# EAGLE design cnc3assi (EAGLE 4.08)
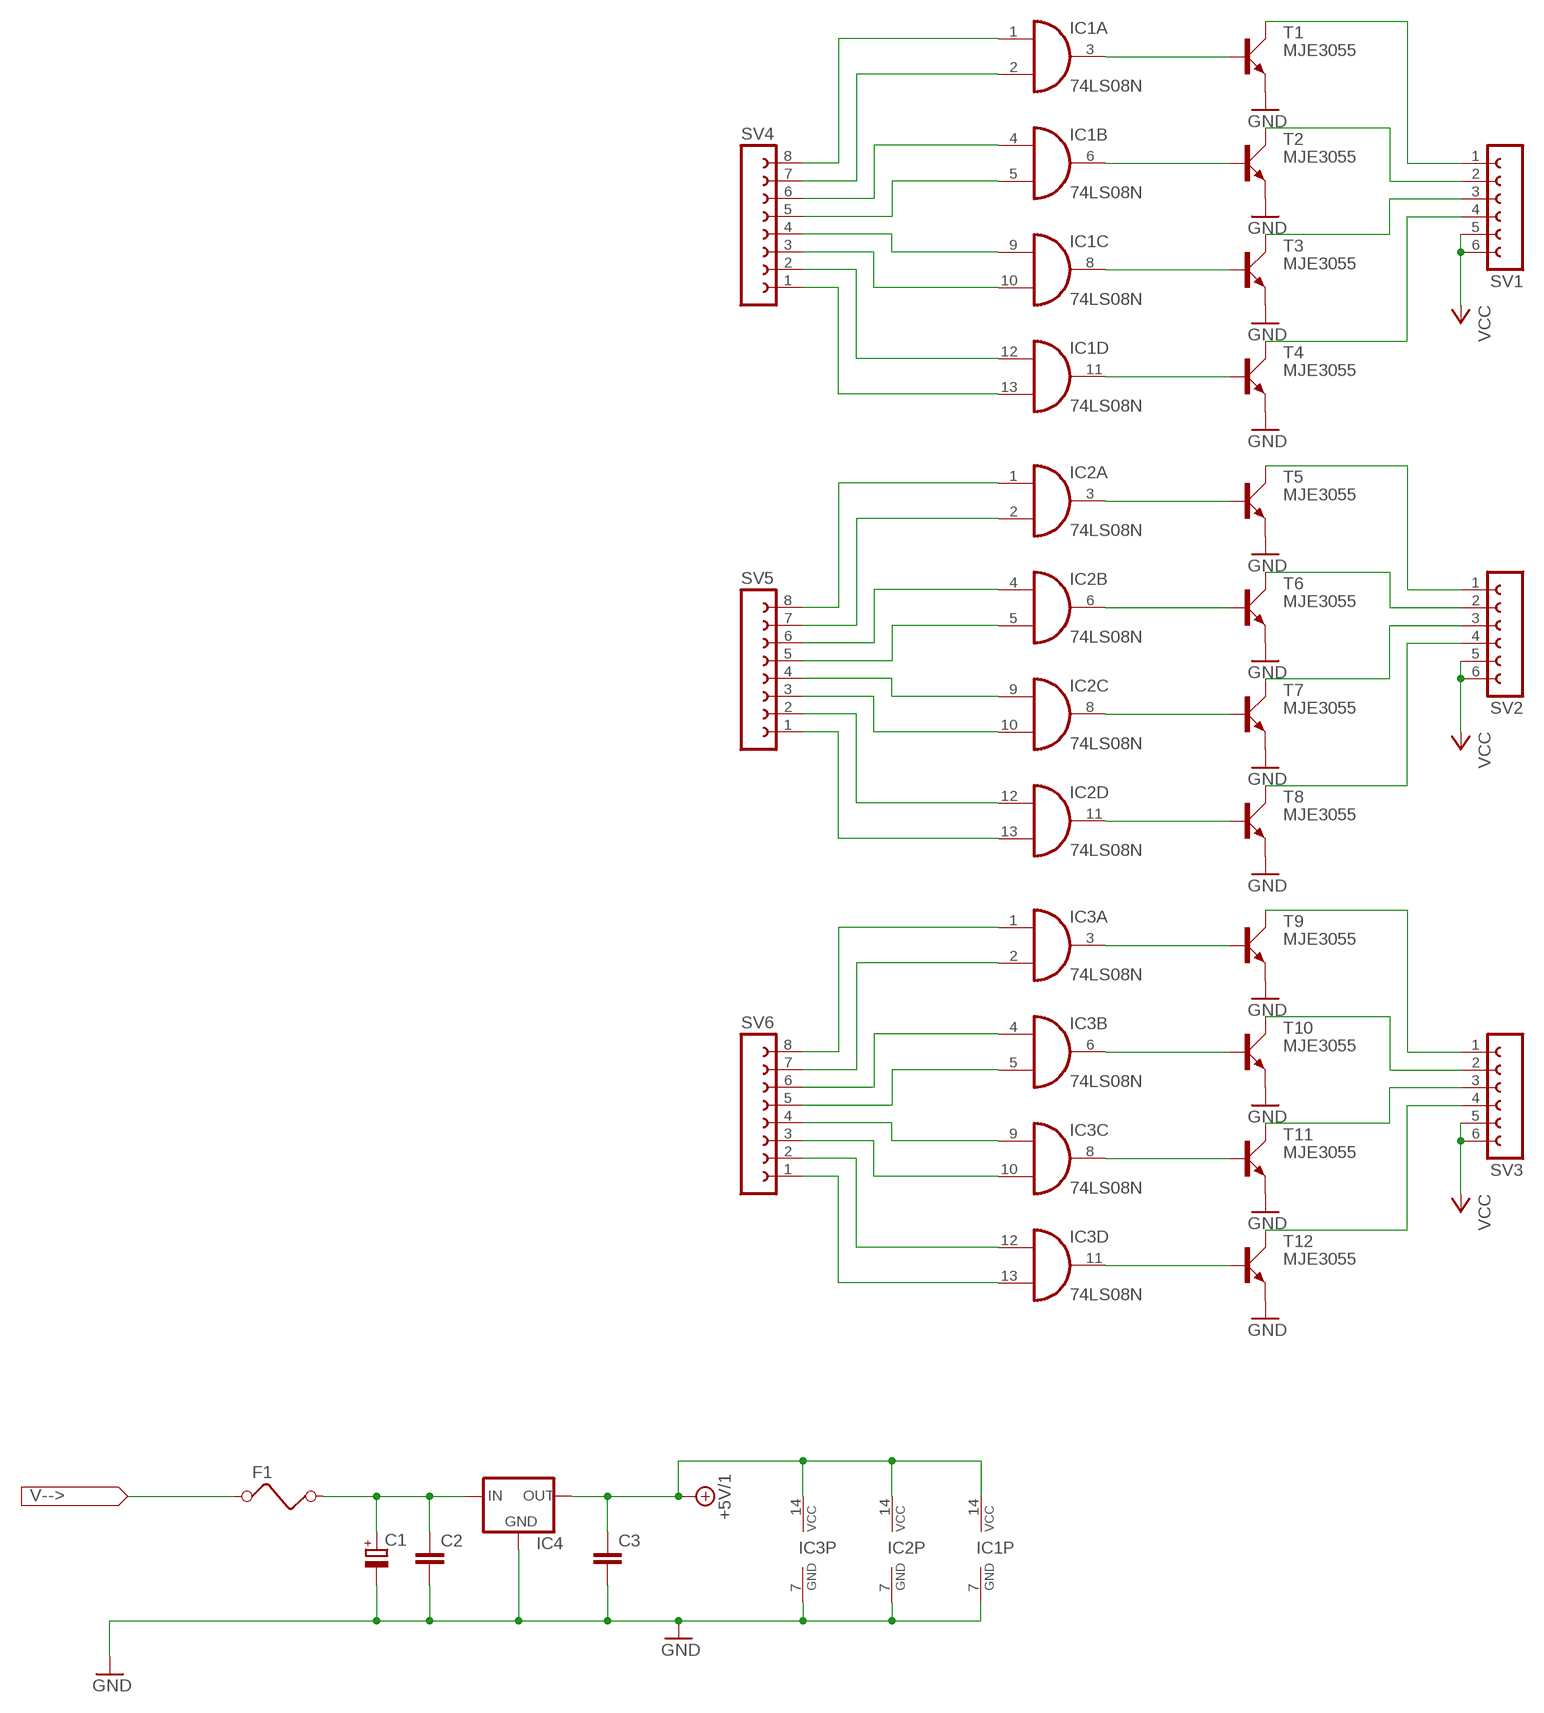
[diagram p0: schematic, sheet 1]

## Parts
C1  CPOL-EUE15-6AXIAL  [E15-6]
C2  C-EU025-030X050  [C025-030X050]
C3  C-EU025-030X050  [C025-030X050]
F1  FUSE  [FUSE]
IC1  74LS08N  [DIL14]
IC2  74LS08N  [DIL14]
IC3  74LS08N  [DIL14]
IC4  78XXS  [78XXS]
SV1  FE06-1  [FE06]
SV2  FE06-1  [FE06]
SV3  FE06-1  [FE06]
SV4  FE08-1  [FE08]
SV5  FE08-1  [FE08]
SV6  FE08-1  [FE08]
T1  MJE3055  [TO220AV]
T2  MJE3055  [TO220AV]
T3  MJE3055  [TO220AV]
T4  MJE3055  [TO220AV]
T5  MJE3055  [TO220AV]
T6  MJE3055  [TO220AV]
T7  MJE3055  [TO220AV]
T8  MJE3055  [TO220AV]
T9  MJE3055  [TO220AV]
T10  MJE3055  [TO220AV]
T11  MJE3055  [TO220AV]
T12  MJE3055  [TO220AV]

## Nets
+5V/1: C3.1 IC1.14(P:VCC) IC2.14(P:VCC) IC3.14(P:VCC) IC4.OUT
GND: C1.- C2.2 C3.2 IC1.7(P:GND) IC2.7(P:GND) IC3.7(P:GND) IC4.GND T1.E T2.E T3.E T4.E T5.E T6.E T7.E T8.E T9.E T10.E T11.E T12.E
N$1: IC1.3(A:O) T1.B
N$2: IC1.6(B:O) T2.B
N$3: IC1.8(C:O) T3.B
N$4: IC1.11(D:O) T4.B
N$5: IC2.3(A:O) T5.B
N$6: IC2.6(B:O) T6.B
N$7: IC2.8(C:O) T7.B
N$8: IC2.11(D:O) T8.B
N$9: IC3.3(A:O) T9.B
N$10: IC3.6(B:O) T10.B
N$11: IC3.8(C:O) T11.B
N$12: IC3.11(D:O) T12.B
N$13: SV1.1 T1.C
N$14: SV1.2 T2.C
N$15: SV1.3 T3.C
N$16: SV1.4 T4.C
N$17: SV2.1 T5.C
N$18: SV2.2 T6.C
N$19: SV2.3 T7.C
N$20: SV2.4 T8.C
N$21: SV3.1 T9.C
N$22: SV3.2 T10.C
N$23: SV3.3 T11.C
N$24: SV3.4 T12.C
N$25: IC1.1(A:I0) SV4.8
N$26: IC1.2(A:I1) SV4.7
N$27: IC1.4(B:I0) SV4.6
N$28: IC1.5(B:I1) SV4.5
N$29: IC1.13(D:I1) SV4.1
N$30: IC1.12(D:I0) SV4.2
N$31: IC1.10(C:I1) SV4.3
N$32: IC1.9(C:I0) SV4.4
N$33: IC2.1(A:I0) SV5.8
N$34: IC2.2(A:I1) SV5.7
N$35: IC2.4(B:I0) SV5.6
N$36: IC2.5(B:I1) SV5.5
N$37: IC2.13(D:I1) SV5.1
N$38: IC2.12(D:I0) SV5.2
N$39: IC2.10(C:I1) SV5.3
N$40: IC2.9(C:I0) SV5.4
N$41: IC3.1(A:I0) SV6.8
N$42: IC3.2(A:I1) SV6.7
N$43: IC3.4(B:I0) SV6.6
N$44: IC3.5(B:I1) SV6.5
N$45: IC3.13(D:I1) SV6.1
N$46: IC3.12(D:I0) SV6.2
N$47: IC3.10(C:I1) SV6.3
N$48: IC3.9(C:I0) SV6.4
N$49: F1.1
N$50: C1.+ C2.1 F1.2 IC4.IN
VCC: SV1.5 SV1.6 SV2.5 SV2.6 SV3.5 SV3.6

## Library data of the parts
C1 = rcl:CPOL-EU: POLARIZED CAPACITOR, European symbol
C2 C3 = rcl:C-EU: CAPACITOR, European symbol
F1 = special:FUSE: FUSE
IC1-IC3 = 74xx-eu:74*08: Quad 2-input AND gate
IC4 = v-reg:78XXS: VOLTAGE REGULATOR
SV1-SV3 = con-lsta:FE06-1: FEMALE HEADER
SV4-SV6 = con-lsta:FE08-1: FEMALE HEADER
T1-T12 = transistor-power:MJE3055: NPN TRANSISTOR

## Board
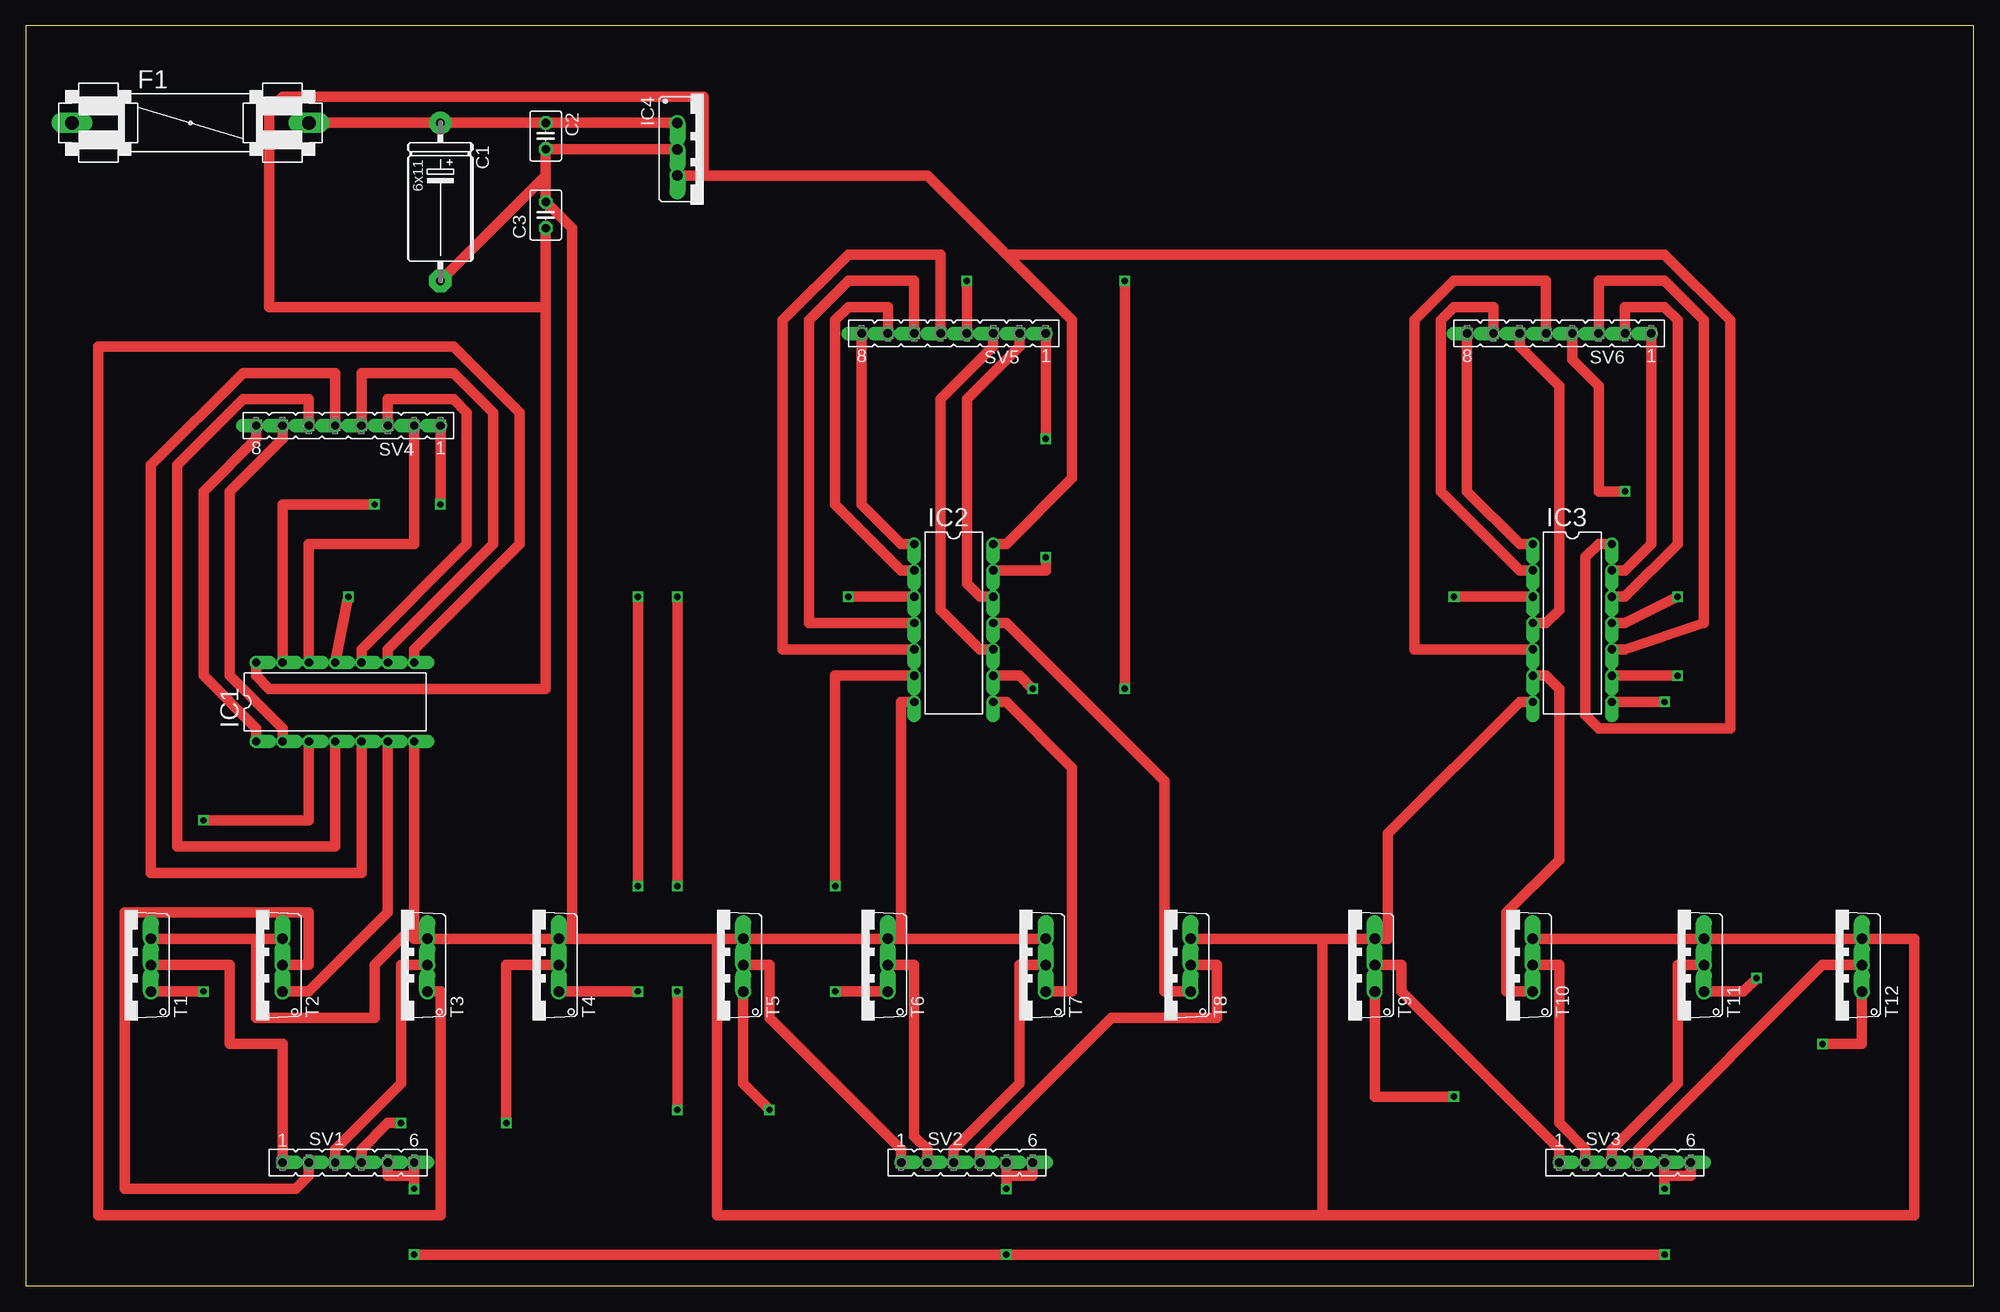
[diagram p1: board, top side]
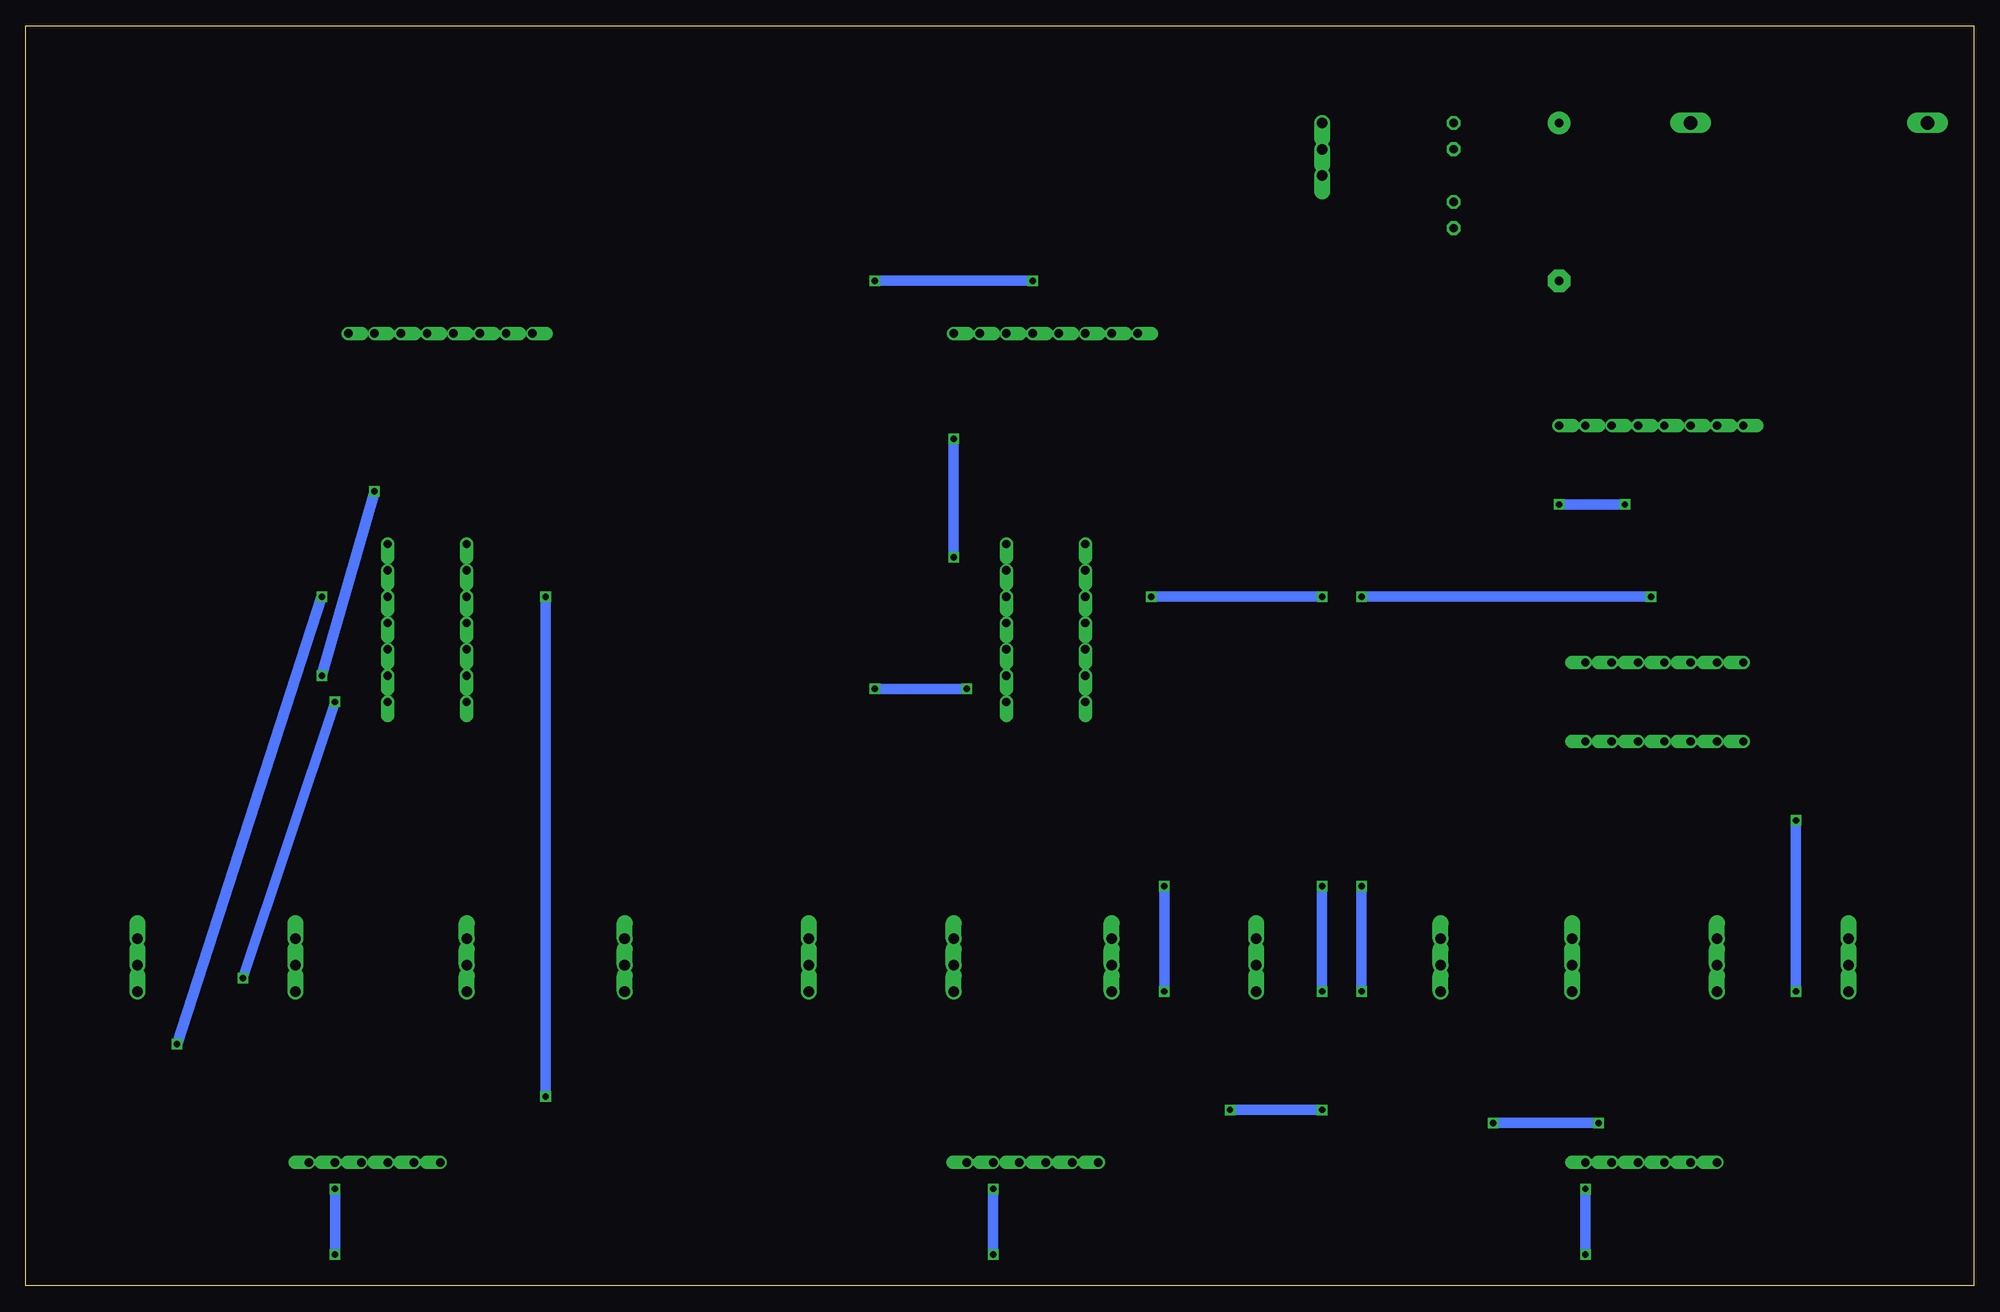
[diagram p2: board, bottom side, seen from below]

Size 187.94 x 121.59 mm. Coordinates in mm from the lower left corner, seen from the top.
Outline: 0,0 187.94,0 187.94,121.59 0,121.59 0,0
Copper layers used: Top, Bottom

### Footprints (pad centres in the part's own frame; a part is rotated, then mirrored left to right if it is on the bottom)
E15-6 = drill 0.813 pad 2.159 round: + -7.62,0 | drill 0.813 pad 2.159 octagon: - 7.62,0
C025-030X050 = drill 0.813 octagon: 1 -1.27,0; 2 1.27,0
FUSE = drill 1.321 long: 1 -11.43,0; 2 11.43,0
DIL14 = drill 0.8 offset: 1 -7.62,-3.81; 2 -5.08,-3.81; 3 -2.54,-3.81; 4 0,-3.81; 5 2.54,-3.81; 6 5.08,-3.81; 7 7.62,-3.81; 8 7.62,3.81; 9 5.08,3.81; 10 2.54,3.81; 11 0,3.81; 12 -2.54,3.81; 13 -5.08,3.81; 14 -7.62,3.81
78XXS = drill 1.016 offset: GND 0,-2.54; IN -2.54,-2.54; OUT 2.54,-2.54
FE06 = drill 0.813 offset: 1 -6.35,0; 2 -3.81,0; 3 -1.27,0; 4 1.27,0; 5 3.81,0; 6 6.35,0
FE08 = drill 0.813 offset: 1 -8.89,0; 2 -6.35,0; 3 -3.81,0; 4 -1.27,0; 5 1.27,0; 6 3.81,0; 7 6.35,0; 8 8.89,0
TO220AV = drill 1.016 offset: B -2.54,-2.54; C 0,-2.54; E 2.54,-2.54

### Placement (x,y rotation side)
C1  40,104.61 270 top
C2  50.16,110.96 270 top
C3  50.16,103.34 90 top
F1  15.87,112.23 0 top
IC1  29.84,56.35 0 top
IC2  89.53,63.97 270 top
IC3  149.22,63.97 270 top
IC4  65.4,109.69 270 top
SV1  31.11,11.9 0 top
SV2  90.8,11.9 0 top
SV3  154.3,11.9 0 top
SV4  31.11,83.02 180 top
SV5  89.53,91.91 180 top
SV6  147.95,91.91 180 top
T1  9.52,30.95 90 top
T2  22.22,30.95 90 top
T3  36.19,30.95 90 top
T4  48.89,30.95 90 top
T5  66.67,30.95 90 top
T6  80.64,30.95 90 top
T7  95.88,30.95 90 top
T8  109.85,30.95 90 top
T9  127.63,30.95 90 top
T10  142.87,30.95 90 top
T11  159.38,30.95 90 top
T12  174.62,30.95 90 top

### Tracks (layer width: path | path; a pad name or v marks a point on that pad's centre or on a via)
+5V/1
  Top 1.016: 50.16,94.45 50.16,57.62 23.49,57.62 22.22,58.89 IC1.14 | 50.16,94.45 C3.1 | 94.61,99.53 86.99,107.15 65.4,107.15 | 94.61,99.53 100.96,93.18 100.96,77.94 94.61,71.59 IC2.14 | 65.4,107.15 64.13,107.15 IC4.OUT | 94.61,99.53 158.11,99.53 164.46,93.18 164.46,53.81 151.76,53.81 150.49,55.08 150.49,70.32 151.76,71.59 IC3.14 | 50.16,94.45 23.49,94.45 23.49,113.5 24.76,114.77 65.4,114.77 65.4,107.15
GND
  Top 1.016: 131.44,33.49 131.44,43.65 144.14,56.35 IC3.7 | 131.44,33.49 T9.E | 84.45,33.49 84.45,56.35 IC2.7 | 84.45,33.49 97.15,33.49 T7.E | 84.45,33.49 T6.E 81.91,33.49 70.48,33.49 T5.E 67.94,33.49 66.67,33.49 | 50.16,107.15 C2.2 | C3.2 50.16,107.15 | C2.2 61.59,109.69 IC4.GND | C2.2 | 50.16,107.15 C1.- | C1.- | 22.22,33.49 23.49,33.49 T2.E | 22.22,33.49 13.33,33.49 T1.E | 37.46,34.76 37.46,33.49 T3.E 40,33.49 50.16,33.49 T4.E 52.7,33.49 | 37.46,34.76 IC1.7 | 22.22,33.49 22.22,25.87 33.65,25.87 33.65,30.95 37.46,34.76 | C3.2 52.7,102.07 52.7,33.49 | C3.2 | 52.7,33.49 66.67,33.49 | 66.67,33.49 66.67,6.82 182.24,6.82 | 182.24,6.82 182.24,33.49 | 182.24,33.49 T12.E 175.89,33.49 163.19,33.49 T11.E 160.65,33.49 146.68,33.49 T10.E 182.24,33.49 | 125.09,33.49 131.44,33.49 | 125.09,33.49 125.09,6.82 182.24,6.82 | 182.24,33.49 182.24,6.82 | 125.09,33.49 T8.E | 125.09,33.49
N$1  (via drill 0.61)
  Top 1.016: T1.B v17.14,28.41 | v17.14,44.92 27.3,44.92 IC1.3
  Bottom 1.016: v17.14,28.41 v17.14,44.92
N$2
  Top 1.016: 34.92,51.27 IC1.6 34.92,36.03 27.3,28.41 26.03,28.41 T2.B
N$3
  Top 1.016: IC1.8 37.46,61.43 47.62,71.59 47.62,84.29 41.27,90.64 6.98,90.64 6.98,6.82 9.52,6.82 40,6.82 40,28.41 T3.B
N$4  (via drill 0.61)
  Top 1.016: v31.11,66.51 IC1.11 | v59.05,38.57 v59.05,66.51 | T4.B v59.05,28.41
  Bottom 1.016: v59.05,66.51 v31.11,66.51 | v59.05,28.41 v59.05,38.57
N$5  (via drill 0.61)
  Top 1.016: T5.B 69.21,19.52 v71.75,16.98 | v62.86,16.98 v62.86,28.41 | v62.86,38.57 v62.86,66.51 | v79.37,66.51 IC2.3
  Bottom 1.016: v62.86,16.98 v71.75,16.98 | v62.86,28.41 v62.86,38.57 | v62.86,66.51 v79.37,66.51
N$6  (via drill 0.61)
  Top 1.016: IC2.6 78.1,58.89 v78.1,38.57 | v78.1,28.41 T6.B
  Bottom 1.016: v78.1,28.41 v78.1,38.57
N$7
  Top 1.016: IC2.8 94.61,56.35 100.96,50 100.96,28.41 99.69,28.41 T7.B
N$8
  Top 1.016: IC2.11 94.61,63.97 109.85,48.73 109.85,28.41 111.12,28.41 T8.B
N$9  (via drill 0.61)
  Top 1.016: v137.79,66.51 IC3.3 | v137.79,18.25 130.17,18.25 T9.B
  Bottom 1.016: v137.79,18.25 v137.79,66.51
N$10
  Top 1.016: IC3.6 146.68,58.89 147.95,57.62 147.95,41.11 142.87,36.03 142.87,28.41 144.14,28.41 T10.B
N$11  (via drill 0.61)
  Top 1.016: T11.B 165.73,28.41 v167,29.68 | v158.11,56.35 IC3.8
  Bottom 1.016: v167,29.68 v158.11,56.35
N$12  (via drill 0.61)
  Top 1.016: IC3.11 154.3,63.97 v159.38,66.51 | v173.35,23.33 177.16,23.33 T12.B
  Bottom 1.016: v173.35,23.33 v159.38,66.51
N$13
  Top 1.016: 13.33,30.95 T1.C | SV1.1 24.76,23.33 19.68,23.33 19.68,30.95 13.33,30.95 | 13.33,30.95
N$14
  Top 1.016: SV1.2 27.3,10.63 26.03,9.36 9.52,9.36 9.52,36.03 27.3,36.03 27.3,30.95 26.03,30.95 T2.C
N$15
  Top 1.016: SV1.3 29.84,13.17 36.19,19.52 36.19,30.95 37.46,30.95 T3.C
N$16  (via drill 0.61)
  Top 1.016: SV1.4 32.38,13.17 34.92,15.71 v36.19,15.71 | v46.35,15.71 46.35,30.95 T4.C
  Bottom 1.016: v36.19,15.71 v46.35,15.71
N$17
  Top 1.016: SV2.1 84.45,13.17 71.75,25.87 71.75,30.95 70.48,30.95 T5.C
N$18
  Top 1.016: SV2.2 86.99,13.17 85.72,14.44 85.72,30.95 84.45,30.95 T6.C
N$19
  Top 1.016: SV2.3 89.53,13.17 95.88,19.52 95.88,30.95 97.15,30.95 T7.C
N$20
  Top 1.016: SV2.4 92.07,13.17 104.77,25.87 114.93,25.87 114.93,30.95 113.66,30.95 T8.C
N$21
  Top 1.016: SV3.1 147.95,13.17 132.71,28.41 132.71,30.95 131.44,30.95 T9.C
N$22
  Top 1.016: SV3.2 150.49,13.17 147.95,15.71 147.95,30.95 146.68,30.95 T10.C
N$23
  Top 1.016: SV3.3 153.03,13.17 159.38,19.52 159.38,30.95 160.65,30.95 T11.C
N$24
  Top 1.016: SV3.4 155.57,13.17 173.35,30.95 175.89,30.95 T12.C
N$25
  Top 1.016: IC1.1 22.22,53.81 17.14,58.89 17.14,76.67 22.22,81.75 SV4.8
N$26
  Top 1.016: IC1.2 24.76,53.81 19.68,58.89 19.68,76.67 24.76,81.75 SV4.7
N$27
  Top 1.016: 29.84,51.27 IC1.4 | SV4.6 27.3,85.56 20.95,85.56 14.6,79.21 14.6,42.38 29.84,42.38 29.84,51.27 | 29.84,51.27
N$28
  Top 1.016: 32.38,51.27 IC1.5 32.38,39.84 12.06,39.84 12.06,79.21 20.95,88.1 29.84,88.1 SV4.5
N$29  (via drill 0.61)
  Top 1.016: IC1.13 24.76,75.4 v33.65,75.4 | v40,75.4 SV4.1
  Bottom 1.016: v33.65,75.4 v40,75.4
N$30
  Top 1.016: 37.46,71.59 SV4.2 | 37.46,71.59 | IC1.12 27.3,71.59 37.46,71.59
N$31
  Top 1.016: IC1.10 32.38,61.43 42.54,71.59 42.54,84.29 41.27,85.56 34.92,85.56 SV4.3
N$32
  Top 1.016: IC1.9 34.92,61.43 45.08,71.59 45.08,84.29 41.27,88.1 32.38,88.1 SV4.4
N$33
  Top 1.016: IC2.1 84.45,71.59 80.64,75.4 SV5.8
N$34
  Top 1.016: IC2.2 84.45,69.05 78.1,75.4 78.1,93.18 79.37,94.45 83.18,94.45 SV5.7
N$35
  Top 1.016: IC2.4 84.45,63.97 75.56,63.97 75.56,93.18 79.37,96.99 85.72,96.99 SV5.6
N$36
  Top 1.016: IC2.5 84.45,61.43 73.02,61.43 73.02,93.18 79.37,99.53 88.26,99.53 SV5.5
N$37  (via drill 0.61)
  Top 1.016: v98.42,81.75 SV5.1 | IC2.13 98.42,69.05 v98.42,70.32
  Bottom 1.016: v98.42,70.32 v98.42,81.75
N$38
  Top 1.016: IC2.12 92.07,66.51 90.8,67.78 90.8,85.56 95.88,90.64 SV5.2
N$39
  Top 1.016: IC2.10 92.07,61.43 88.26,65.24 88.26,85.56 93.34,90.64 SV5.3
N$40  (via drill 0.61)
  Top 1.016: IC2.9 95.88,58.89 v97.15,57.62 | v106.04,57.62 v106.04,96.99 | v90.8,96.99 SV5.4
  Bottom 1.016: v97.15,57.62 v106.04,57.62 | v106.04,96.99 v90.8,96.99
N$41
  Top 1.016: IC3.1 144.14,71.59 139.06,76.67 SV6.8
N$42
  Top 1.016: IC3.2 144.14,69.05 136.52,76.67 136.52,93.18 137.79,94.45 141.6,94.45 SV6.7
N$43
  Top 1.016: IC3.4 146.68,63.97 147.95,65.24 147.95,86.83 144.14,90.64 SV6.6
N$44
  Top 1.016: IC3.5 144.14,61.43 133.98,61.43 133.98,93.18 137.79,96.99 146.68,96.99 SV6.5
N$45
  Top 1.016: IC3.13 154.3,69.05 156.84,71.59 SV6.1
N$46
  Top 1.016: IC3.12 154.3,66.51 159.38,71.59 159.38,93.18 158.11,94.45 154.3,94.45 SV6.2
N$47
  Top 1.016: IC3.10 154.3,61.43 161.92,63.97 161.92,93.18 158.11,96.99 151.76,96.99 SV6.3
N$48  (via drill 0.61)
  Top 1.016: IC3.9 v159.38,58.89 | v154.3,76.67 151.76,76.67 151.76,86.83 149.22,89.37 SV6.4
  Bottom 1.016: v159.38,58.89 v154.3,76.67
N$50
  Top 1.016: C1.+ C2.1 | C2.1 61.59,112.23 IC4.IN | C2.1 | C1.+ 28.57,112.23 F1.2 | C1.+
VCC  (via drill 0.61)
  Top 1.016: SV1.5 34.92,10.63 37.46,10.63 SV1.6 v37.46,9.36 | 94.61,10.63 97.15,10.63 SV2.6 | 94.61,10.63 | SV3.6 160.65,10.63 158.11,10.63 SV3.5 v158.11,9.36 | v37.46,3.01 v94.61,3.01 v158.11,3.01 | v94.61,9.36 94.61,10.63 | 94.61,10.63 SV2.5
  Bottom 1.016: v37.46,3.01 v37.46,9.36 | v94.61,3.01 v94.61,9.36 | v158.11,3.01 v158.11,9.36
